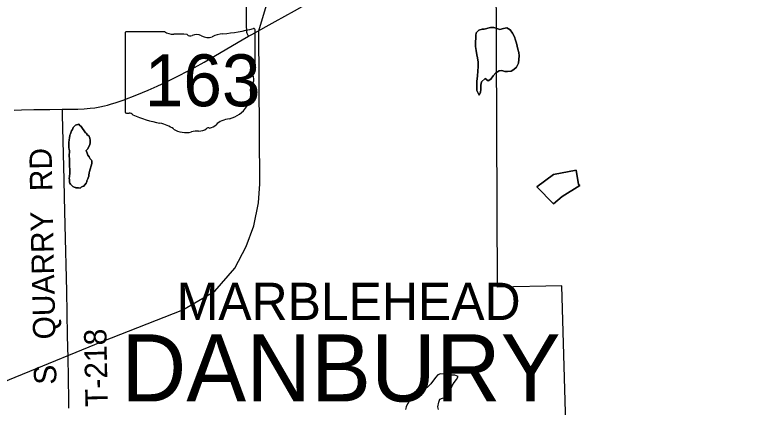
# Model space of a CAD drawing. Extents: x -12 to 34, y 0 to 22.
# Drawn here: x 5.999 to 7.899, y 17.107 to 18.102 of the extents above; entities that cross this region are included whole.
import ezdxf

# ---------------------------------------------------------------- set-up
doc = ezdxf.new("R2010")
doc.units = 0
for name, color, linetype in [('GM_X_Airport_Location_Class_2', 7, 'Continuous'), ('GM_X_Corporation', 7, 'Continuous'), ('GM_X_County_Road_Text', 7, 'Continuous'), ('GM_X_Major_Lake', 7, 'Continuous'), ('GM_X_Major_River', 7, 'Continuous'), ('GM_X_Minor_Lake', 7, 'Continuous'), ('GM_X_Township', 7, 'Continuous'), ('GM_X_Township_Road', 7, 'Continuous'), ('GM_X_Township_Road_Text', 7, 'Continuous'), ('GM_X_Township_Subdivision_Text', 7, 'Continuous'), ('GM_X_Township_Text', 7, 'Continuous')]:
    doc.layers.add(name, color=color, linetype=linetype)

msp = doc.modelspace()

# ---------------------------------------------------------------- linework, layer by layer
at = {"layer": 'GM_X_Airport_Location_Class_2'}
msp.add_lwpolyline([(7.4121, 16.5387), (7.3864, 17.4151), (7.2233, 17.4111), (7.2195, 18.2227)], dxfattribs=at)
at = {"layer": 'GM_X_Corporation'}
msp.add_lwpolyline([(5.8151, 17.1077), (6.2198, 17.2736), (6.4243, 17.354), (6.5061, 17.4016), (6.5567, 17.4596), (6.585, 17.5147), (6.6051, 17.5675), (6.6162, 17.6256), (6.62, 17.674), (6.6177, 18.0624), (6.6371, 18.1271), (6.6557, 18.1606), (6.7018, 18.1993), (6.7606, 18.2254), (7.0425, 18.3601), (7.0932, 18.3811), (7.1588, 18.3984), (7.2206, 18.4089), (7.2787, 18.4071), (7.5718, 18.3347), (7.6466, 18.3322), (7.7363, 18.3372), (7.8525, 18.3514), (8.033, 18.3768)], dxfattribs=at)
at = {"layer": 'GM_X_Major_Lake'}
msp.add_lwpolyline([(5.9967, 17.8611), (6.0154, 17.862), (6.0465, 17.8625), (6.0869, 17.8627), (6.1187, 17.8632), (6.1583, 17.8637), (6.1738, 17.8643), (6.1893, 17.8655), (6.2016, 17.867), (6.2137, 17.869), (6.2258, 17.8714), (6.2335, 17.8734), (6.2409, 17.8756), (6.2556, 17.8803), (6.2732, 17.8865), (6.3079, 17.9001), (6.3366, 17.9119), (6.3593, 17.9219), (6.3846, 17.9338), (6.4152, 17.9491), (6.4539, 17.969), (6.4784, 17.9824), (6.575, 18.0389), (6.5914, 18.0482), (6.5993, 18.0527), (6.6592, 18.0856), (6.7079, 18.1131)], dxfattribs=at)
at = {"layer": 'GM_X_Major_River'}
for points in [[(6.5914, 18.0482), (6.5896, 18.0516), (6.5884, 18.0538), (6.5877, 18.0558), (6.5873, 18.058), (6.5864, 18.0788), (6.5862, 18.113), (6.586, 18.1286), (6.5852, 18.169), (6.5852, 18.1777)], [(6.1356, 17.1039), (6.1355, 17.1236), (6.1345, 17.181), (6.1333, 17.2337), (6.1328, 17.2586), (6.1322, 17.2896), (6.1299, 17.4013), (6.126, 17.5689), (6.1242, 17.6403), (6.1231, 17.6838), (6.1192, 17.8489), (6.1188, 17.8599), (6.1187, 17.8632)]]:
    msp.add_lwpolyline(points, dxfattribs=at)
at = {"layer": 'GM_X_Minor_Lake'}
for p, q in [((7.3868, 17.6413), (7.4316, 17.6695)), ((7.0887, 17.1906), (7.0788, 17.1912))]:
    msp.add_line(p, q, dxfattribs=at)
for points in [[(7.1894, 18.0668), (7.2054, 18.0703), (7.2134, 18.0706), (7.2214, 18.0678), (7.2293, 18.0654), (7.2381, 18.068), (7.2465, 18.0694), (7.2548, 18.0647), (7.2615, 18.0566), (7.266, 18.047), (7.2689, 18.0386), (7.2714, 18.031), (7.2732, 18.0229), (7.275, 18.0153), (7.2768, 18.0073), (7.2778, 17.9989), (7.2772, 17.9894), (7.276, 17.9803), (7.2712, 17.9701), (7.2643, 17.9637), (7.2574, 17.96), (7.2486, 17.9586), (7.2418, 17.9591), (7.2342, 17.9611), (7.2273, 17.9608), (7.2189, 17.9556), (7.2119, 17.9481), (7.2061, 17.9398), (7.1992, 17.9354), (7.1916, 17.9408), (7.1824, 17.9326), (7.1811, 17.9242), (7.1809, 17.9132), (7.1801, 17.9064), (7.1769, 17.8992), (7.1703, 17.9107), (7.1708, 17.924), (7.171, 17.9339), (7.172, 17.9476), (7.1739, 17.9719), (7.1736, 17.9822), (7.1727, 17.9936), (7.1709, 18.0016), (7.1692, 18.0119), (7.1674, 18.0226), (7.1672, 18.0355), (7.1677, 18.0423), (7.1678, 18.0503), (7.1691, 18.0572), (7.176, 18.0639), (7.1845, 18.0665), (7.189, 18.0667), (7.1894, 18.0668)], [(7.1894, 18.0668), (7.189, 18.0667), (7.1845, 18.0665), (7.176, 18.0639), (7.1691, 18.0572), (7.1678, 18.0503), (7.1677, 18.0423), (7.1672, 18.0355), (7.1674, 18.0226), (7.1692, 18.0119), (7.1709, 18.0016), (7.1727, 17.9936), (7.1736, 17.9822), (7.1739, 17.9719), (7.172, 17.9476), (7.171, 17.9339), (7.1708, 17.924), (7.1703, 17.9107), (7.1769, 17.8992), (7.1801, 17.9064), (7.1809, 17.9132), (7.1811, 17.9242), (7.1824, 17.9326), (7.1916, 17.9408), (7.1992, 17.9354), (7.2061, 17.9398), (7.2119, 17.9481)], [(7.2119, 17.9481), (7.2189, 17.9556), (7.2273, 17.9608), (7.2342, 17.9611), (7.2418, 17.9591), (7.2486, 17.9586), (7.2574, 17.96), (7.2643, 17.9637), (7.2712, 17.9701), (7.276, 17.9803), (7.2772, 17.9894), (7.2778, 17.9989), (7.2768, 18.0073), (7.275, 18.0153), (7.2732, 18.0229), (7.2714, 18.031), (7.2689, 18.0386), (7.266, 18.047), (7.2615, 18.0566), (7.2548, 18.0647), (7.2465, 18.0694), (7.2381, 18.068), (7.2293, 18.0654), (7.2214, 18.0678), (7.2134, 18.0706), (7.2054, 18.0703), (7.1894, 18.0668)], [(6.1778, 17.8036), (6.1664, 17.8195), (6.1627, 17.8226), (6.1608, 17.8249), (6.1525, 17.8223), (6.1463, 17.8167), (6.1443, 17.8114), (6.142, 17.8084), (6.1408, 17.8058), (6.1392, 17.8005), (6.138, 17.7971), (6.1368, 17.7899), (6.136, 17.7865), (6.1355, 17.7781), (6.1354, 17.7747), (6.1353, 17.7683), (6.1357, 17.7652), (6.136, 17.7614), (6.1367, 17.7572), (6.1365, 17.7439), (6.1372, 17.7375), (6.1371, 17.7329), (6.1367, 17.7295), (6.137, 17.7249), (6.1369, 17.72), (6.1372, 17.7158), (6.1376, 17.7128), (6.1374, 17.6984), (6.1369, 17.6949), (6.1369, 17.6915), (6.1364, 17.6877), (6.1368, 17.6839), (6.1367, 17.6801), (6.137, 17.6775), (6.1378, 17.6756), (6.1393, 17.6733), (6.1404, 17.6717), (6.1449, 17.6682), (6.1456, 17.6671), (6.1475, 17.6659), (6.1486, 17.6652), (6.1516, 17.6647), (6.152, 17.664), (6.1531, 17.6639), (6.1543, 17.6636)], [(6.1778, 17.8036), (6.1806, 17.8014), (6.1809, 17.7991), (6.1847, 17.7964), (6.1866, 17.7949), (6.1873, 17.7937), (6.1877, 17.7922), (6.1884, 17.7895), (6.1891, 17.785), (6.1893, 17.7781), (6.1885, 17.7736), (6.1858, 17.7675), (6.1823, 17.7619), (6.1796, 17.7581), (6.1799, 17.7559), (6.1817, 17.752), (6.1839, 17.7463), (6.1865, 17.7421), (6.1891, 17.7375), (6.1917, 17.7348), (6.1932, 17.7336), (6.1936, 17.7325), (6.1939, 17.7302), (6.1939, 17.7257), (6.1923, 17.7192), (6.1895, 17.7109), (6.1879, 17.7052), (6.1871, 17.7018), (6.1867, 17.7007), (6.1862, 17.6969), (6.1858, 17.6935), (6.1842, 17.6893), (6.1838, 17.6863), (6.1819, 17.6829), (6.1811, 17.6814), (6.1807, 17.6787), (6.1791, 17.6754), (6.176, 17.6712), (6.1737, 17.6678), (6.1718, 17.6675), (6.1668, 17.6653), (6.1641, 17.663), (6.16, 17.6635), (6.1543, 17.6636), (6.1531, 17.6639), (6.152, 17.664), (6.1516, 17.6647), (6.1486, 17.6652), (6.1475, 17.6659), (6.1456, 17.6671), (6.1449, 17.6682), (6.1404, 17.6717), (6.1393, 17.6733), (6.1378, 17.6756), (6.137, 17.6775), (6.1367, 17.6801), (6.1368, 17.6839), (6.1364, 17.6877), (6.1369, 17.6915), (6.1369, 17.6949), (6.1374, 17.6984), (6.1376, 17.7128), (6.1372, 17.7158), (6.1369, 17.72), (6.137, 17.7249), (6.1367, 17.7295), (6.1371, 17.7329), (6.1372, 17.7375), (6.1365, 17.7439), (6.1367, 17.7572), (6.136, 17.7614), (6.1357, 17.7652), (6.1353, 17.7683), (6.1354, 17.7747), (6.1355, 17.7781), (6.136, 17.7865), (6.1368, 17.7899), (6.138, 17.7971), (6.1392, 17.8005), (6.1408, 17.8058), (6.142, 17.8084), (6.1443, 17.8114), (6.1463, 17.8167), (6.1525, 17.8223), (6.1608, 17.8249), (6.1627, 17.8226), (6.1664, 17.8195), (6.1778, 17.8036)], [(6.1543, 17.6636), (6.16, 17.6635), (6.1641, 17.663), (6.1668, 17.6653), (6.1718, 17.6675), (6.1737, 17.6678), (6.176, 17.6712), (6.1791, 17.6754), (6.1807, 17.6787), (6.1811, 17.6814), (6.1819, 17.6829), (6.1838, 17.6863), (6.1842, 17.6893), (6.1858, 17.6935), (6.1862, 17.6969), (6.1867, 17.7007), (6.1871, 17.7018), (6.1879, 17.7052), (6.1895, 17.7109), (6.1923, 17.7192), (6.1939, 17.7257), (6.1939, 17.7302), (6.1936, 17.7325), (6.1932, 17.7336), (6.1917, 17.7348), (6.1891, 17.7375), (6.1865, 17.7421), (6.1839, 17.7463), (6.1817, 17.752), (6.1799, 17.7559), (6.1796, 17.7581), (6.1823, 17.7619), (6.1858, 17.7675), (6.1885, 17.7736), (6.1893, 17.7781), (6.1891, 17.785), (6.1884, 17.7895), (6.1877, 17.7922), (6.1873, 17.7937), (6.1866, 17.7949), (6.1847, 17.7964), (6.1809, 17.7991), (6.1806, 17.8014), (6.1778, 17.8036)], [(7.4316, 17.6695), (7.4283, 17.6722), (7.4224, 17.7088), (7.3652, 17.6975), (7.3228, 17.6662), (7.3648, 17.6233), (7.3868, 17.6413)], [(7.4319, 17.6697), (7.3868, 17.6413), (7.3648, 17.6233), (7.3228, 17.6662), (7.3652, 17.6975), (7.4224, 17.7088), (7.4283, 17.6722), (7.4316, 17.6695)], [(7.0788, 17.1912), (7.0716, 17.189), (7.0654, 17.1818), (7.0537, 17.166), (7.0471, 17.1589), (7.0391, 17.1522), (7.0313, 17.1458), (7.0237, 17.1406), (7.0148, 17.1343), (7.0063, 17.1275), (6.999, 17.1216), (6.9943, 17.1148), (6.9912, 17.1076), (6.9899, 17.1004)], [(7.0733, 17.1007), (7.0715, 17.1076), (7.0739, 17.1193), (7.0767, 17.1269), (7.0836, 17.1298), (7.0908, 17.1301), (7.0977, 17.1323), (7.1012, 17.1391), (7.1037, 17.1474), (7.1053, 17.1546), (7.1088, 17.1622), (7.1135, 17.1697), (7.119, 17.1773), (7.1229, 17.1844), (7.1149, 17.1876), (7.1058, 17.1881), (7.0967, 17.1894), (7.0887, 17.1906)]]:
    msp.add_lwpolyline(points, dxfattribs=at)
at = {"layer": 'GM_X_Township'}
for points in [[(6.6071, 18.057), (6.6592, 18.0856), (6.7079, 18.1131), (6.786, 18.1581), (6.8613, 18.2018), (6.8641, 18.2033)], [(5.9967, 17.8611), (6.0154, 17.862), (6.0465, 17.8625), (6.0869, 17.8627), (6.1187, 17.8632), (6.1583, 17.8637), (6.1738, 17.8643), (6.1893, 17.8655), (6.2016, 17.867), (6.2137, 17.869), (6.2258, 17.8714), (6.2335, 17.8734), (6.2409, 17.8756), (6.2556, 17.8803), (6.2732, 17.8865)]]:
    msp.add_lwpolyline(points, dxfattribs=at)
at = {"layer": 'GM_X_Township_Text'}
for p, q in [((6.378, 18.06), (6.2814, 18.06)), ((6.6078, 17.9603), (6.6078, 18.065)), ((6.2782, 18.0566), (6.2782, 17.8565)), ((6.6077, 17.9603), (6.6078, 17.9603))]:
    msp.add_line(p, q, dxfattribs=at)
for centre, major_axis, start_param, end_param in [((6.282, 18.057), (0.00382, 0), 1.712693, 3.28349), ((6.4009, 18.0833), (0.037, 0), 4.042523, 4.731795), ((6.4904, 18.3329), (0.3495, 0), 4.814394, 5.042369), ((6.6041, 18.0654), (0.00367, 0), 6.141152, 7.989035), ((6.4132, 17.9477), (0.133, 0), 1.404758, 1.657858), ((6.4434, 18.058), (0.0107, 0), 3.836095, 5.185415), ((6.4591, 18.0349), (0.0222, 0), 0.950623, 2.079405), ((6.4878, 18.0666), (0.0267, 0), 4.081561, 5.145723), ((6.535, 17.9989), (0.0703, 0), 1.699011, 2.107814), ((6.6069, 17.9526), (0.00568, 0), 1.883978, 3.671073), ((6.5708, 17.9394), (0.0341, 0), 5.934695, 6.695948), ((6.6039, 17.9599), (0.00393, 0), 5.05454, 6.418171), ((6.6209, 17.9165), (0.0248, 0), 2.387724, 3.262537), ((6.51, 17.9032), (0.0874, 0), 5.101752, 6.440018), ((6.282, 17.856), (0.00385, 0), 3.00124, 4.508301), ((6.2826, 17.8765), (0.0294, 0), 4.665946, 4.897461), ((6.2886, 17.8449), (0.0106, 0), 0.519207, 1.627899), ((6.4224, 18.0247), (0.2524, 0), 4.195997, 4.488961), ((6.5468, 17.8003), (0.0479, 0), 1.647645, 2.488434), ((6.3472, 17.7666), (0.079, 0), 0.823519, 1.323587), ((6.4326, 17.8439), (0.0501, 0), 4.026481, 4.996735), ((6.4652, 17.8289), (0.0267, 0), 4.691044, 5.507374), ((6.4894, 17.8096), (0.00752, 0), 1.147584, 2.315152), ((6.4862, 17.8371), (0.0282, 0), 4.937069, 5.64225), ((6.4615, 17.7747), (0.0412, 0), 1.495662, 1.94098)]:
    msp.add_ellipse(centre, major_axis=major_axis, ratio=0.8, start_param=start_param, end_param=end_param, dxfattribs=at)

# ---------------------------------------------------------------- texts
at = {"layer": 'GM_X_County_Road_Text'}
for s, height, rotation, p in [('RD', 0.05682, 90.9815, (6.0935, 17.6555)), ('QUARRY', 0.05682, 91.2633, (6.1016, 17.2793)), ('T-218', 0.05682, 91.1284, (6.2343, 17.1079)), ('S', 0.0568, 91.2447, (6.1041, 17.1643))]:
    msp.add_text(s, height=height, rotation=rotation, dxfattribs=at).set_placement(p)
at = {"layer": 'GM_X_Township_Road'}
msp.add_text('DANBURY', height=0.17045, rotation=0, dxfattribs=at).set_placement((6.2687, 17.1212))
at = {"layer": 'GM_X_Township_Road_Text'}
for s in ['s', 'r']:
    msp.add_text(s, height=0.000189, dxfattribs=at).set_placement((6.4393, 17.9432))
msp.add_text('163', height=0.000189, rotation=0, dxfattribs=at).set_placement((6.3724, 17.9294))
at = {"layer": 'GM_X_Township_Subdivision_Text'}
msp.add_text('MARBLEHEAD', height=0.0947, rotation=0, dxfattribs=at).set_placement((6.4091, 17.328))
at = {"layer": 'GM_X_Township_Text'}
msp.add_text('163', height=0.13184, dxfattribs=at).set_placement((6.3277, 17.8706))

doc.saveas('drawing.dxf')
